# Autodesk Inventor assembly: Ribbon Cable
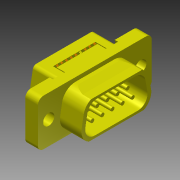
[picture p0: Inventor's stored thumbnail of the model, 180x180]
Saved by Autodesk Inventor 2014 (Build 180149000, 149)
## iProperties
Created: 2006-11
Part Number: Ribbon Cable
Document SubType Name: Assembly
Designer: floress
Mass: 2.31161 g
Surface Area: 32.9407 cm^2
Volume: 2.31161 cm^3
Density: 1 g/cm^3
ParentFileIdentifier: 5|1|0|0|122|2|0|0|80|0|65|0|84|0|72|0|83|0|59|0|67|0|58|0|92|0|80|0|114|0|111|0|103|0|114|0|97|0|109|0|32|0|70|0|105|0|108|0|101|0|115|0|92|0|65|0|117|0|116|0|1
HarnessSettings: <HarnessSettings><Defaults><Segments><Diameter value="0.200 in" fromwires="True"/><Offset value="0.100 in"/><ColorStyle value="Blue"/><RoundUp value=""/><BendRa
CableFileVersion: 12.0.4
Author: floress
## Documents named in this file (3)
- C:\Users\iTools\Desktop\tutorial files\Cable and Harness\Enclosure_Assembly\AIP\Cable and Harness\Ribbon Cable.iam
- C:\Users\iTools\Desktop\tutorial files\Cable and Harness\Enclosure_Assembly\AIP\Cable and Harness\Ribbon Cable.ipt
- C:\Users\iTools\Desktop\tutorial files\Cable and Harness\D-Sub Ribbon.ipt
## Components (2 placed, 2 different names)
1. D-Sub Ribbon:1
2. Ribbon Cable
